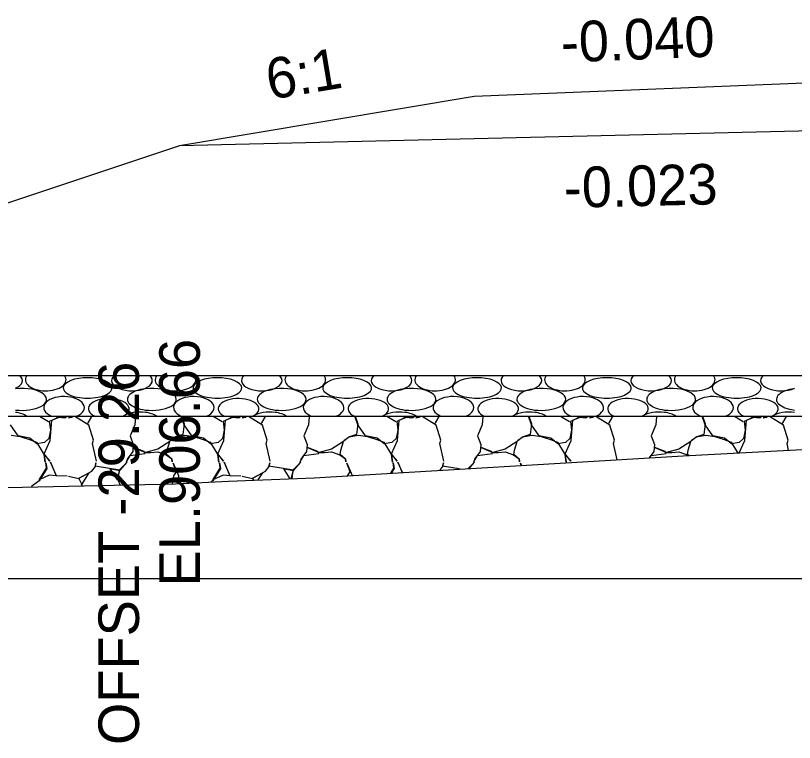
# Model space of a CAD drawing. Extents: x -26 to 4781, y -31 to 24738.
# Drawn here: x 2266.7 to 2285.89, y 14995.97 to 15013.86 of the extents above; entities that cross this region are included whole.
import ezdxf

# ---------------------------------------------------------------- set-up
doc = ezdxf.new("R2010")
doc.units = 0
for name, color, linetype in [('DESIGN - SHEET - Light Grid', 7, 'Continuous'), ('DESIGN - TRANSPORTATION - Proposed Layout Patterning', 7, 'Continuous'), ('DESIGN - TYPICAL - Finished Grade and Subgrade', 7, 'Continuous'), ('DESIGN - TYPICAL - Finished Grade Slopes Text', 7, 'Continuous'), ('DESIGN - TYPICAL - Subgrade Cross Slope Text', 7, 'Continuous'), ('DESIGN - TYPICAL - Subgrade Tie Text', 7, 'Continuous'), ('GEOTECHNICAL – SCRATCH – Level 1', 7, 'Continuous'), ('SURVEY - GROUND - Top of Ground', 7, 'Continuous')]:
    doc.layers.add(name, color=color, linetype=linetype)

msp = doc.modelspace()

# ---------------------------------------------------------------- linework, layer by layer
at = {"layer": 'DESIGN - SHEET - Light Grid'}
msp.add_line((2000, 15000), (2300, 15000), dxfattribs=at)
at = {"layer": 'DESIGN - TRANSPORTATION - Proposed Layout Patterning'}
for p, q in [((2267.288, 15004), (2267.507, 15003.869)), ((2271.568, 15004), (2271.787, 15003.869)), ((2275.848, 15004), (2276.067, 15003.869)), ((2280.128, 15004), (2280.347, 15003.869)), ((2284.408, 15004), (2284.627, 15003.869))]:
    msp.add_line(p, q, dxfattribs=at)
for points in [[(2266.587, 15003.529), (2266.807, 15003.499), (2267.037, 15003.429), (2267.207, 15003.359), (2267.397, 15003.049), (2267.427, 15002.869), (2267.397, 15003.059), (2267.537, 15002.889), (2267.397, 15003.069), (2267.547, 15003.399), (2267.587, 15003.899), (2267.767, 15003.979), (2267.897, 15003.959), (2267.977, 15003.999), (2267.927, 15003.959), (2267.777, 15003.989), (2267.607, 15003.899), (2267.527, 15003.869), (2267.557, 15003.659), (2267.517, 15003.449), (2267.407, 15003.349), (2267.217, 15003.319), (2267.047, 15003.459), (2266.757, 15003.519), (2266.567, 15003.789)], [(2268.687, 15002.889), (2268.587, 15003.329), (2268.617, 15003.409), (2268.497, 15003.779), (2268.157, 15003.989), (2267.997, 15003.959), (2268.087, 15003.979), (2268.083, 15004)], [(2268.571, 15004), (2268.477, 15003.829), (2268.576, 15004)], [(2269.64, 15004), (2269.647, 15003.989), (2269.637, 15003.789), (2269.517, 15003.519), (2269.597, 15003.299), (2269.587, 15003.129), (2269.447, 15002.939), (2269.427, 15002.879), (2269.517, 15003.029), (2269.887, 15003.079), (2269.867, 15003.129), (2269.607, 15003.229), (2269.897, 15003.109), (2270.027, 15003.109), (2270.197, 15003.119), (2270.407, 15003.049), (2270.547, 15002.949), (2270.557, 15002.879), (2270.547, 15002.939), (2270.417, 15003.059), (2270.427, 15003.159), (2270.497, 15003.379), (2270.197, 15003.189), (2269.897, 15003.109)], [(2270.781, 15004), (2270.847, 15003.809), (2270.817, 15003.549), (2270.647, 15003.489), (2270.507, 15003.389), (2270.627, 15003.489), (2270.867, 15003.529), (2271.087, 15003.499), (2271.317, 15003.429), (2271.487, 15003.359), (2271.677, 15003.049), (2271.707, 15002.869), (2271.677, 15003.059), (2271.817, 15002.889), (2271.677, 15003.069), (2271.827, 15003.399), (2271.867, 15003.899), (2272.047, 15003.979), (2272.177, 15003.959), (2272.257, 15003.999), (2272.207, 15003.959), (2272.057, 15003.989), (2271.887, 15003.899), (2271.807, 15003.869), (2271.837, 15003.659), (2271.797, 15003.449), (2271.687, 15003.349), (2271.497, 15003.319), (2271.327, 15003.459), (2271.037, 15003.519), (2270.847, 15003.789), (2270.779, 15004)], [(2272.967, 15002.889), (2272.867, 15003.329), (2272.897, 15003.409), (2272.777, 15003.779), (2272.437, 15003.989), (2272.277, 15003.959), (2272.367, 15003.979), (2272.363, 15004)], [(2272.851, 15004), (2272.757, 15003.829), (2272.856, 15004)], [(2273.92, 15004), (2273.927, 15003.989), (2273.917, 15003.789), (2273.797, 15003.519), (2273.877, 15003.299), (2273.867, 15003.129), (2273.727, 15002.939), (2273.707, 15002.879), (2273.797, 15003.029), (2274.167, 15003.079), (2274.147, 15003.129), (2273.887, 15003.229), (2274.177, 15003.109), (2274.307, 15003.109), (2274.477, 15003.119), (2274.687, 15003.049), (2274.827, 15002.949), (2274.837, 15002.879), (2274.827, 15002.939), (2274.697, 15003.059), (2274.707, 15003.159), (2274.777, 15003.379), (2274.477, 15003.189), (2274.177, 15003.109)], [(2275.061, 15004), (2275.127, 15003.809), (2275.097, 15003.549), (2274.927, 15003.489), (2274.787, 15003.389), (2274.907, 15003.489), (2275.147, 15003.529), (2275.367, 15003.499), (2275.597, 15003.429), (2275.767, 15003.359), (2275.957, 15003.049), (2275.987, 15002.869), (2275.957, 15003.059), (2276.097, 15002.889), (2275.957, 15003.069), (2276.107, 15003.399), (2276.147, 15003.899), (2276.327, 15003.979), (2276.457, 15003.959), (2276.537, 15003.999), (2276.487, 15003.959), (2276.337, 15003.989), (2276.167, 15003.899), (2276.087, 15003.869), (2276.117, 15003.659), (2276.077, 15003.449), (2275.967, 15003.349), (2275.777, 15003.319), (2275.607, 15003.459), (2275.317, 15003.519), (2275.127, 15003.789), (2275.059, 15004)], [(2277.247, 15002.889), (2277.147, 15003.329), (2277.177, 15003.409), (2277.057, 15003.779), (2276.717, 15003.989), (2276.557, 15003.959), (2276.647, 15003.979), (2276.643, 15004)], [(2277.131, 15004), (2277.037, 15003.829), (2277.136, 15004)], [(2278.2, 15004), (2278.207, 15003.989), (2278.197, 15003.789), (2278.077, 15003.519), (2278.157, 15003.299), (2278.147, 15003.129), (2278.007, 15002.939), (2277.987, 15002.879), (2278.077, 15003.029), (2278.447, 15003.079), (2278.427, 15003.129), (2278.167, 15003.229), (2278.457, 15003.109), (2278.587, 15003.109), (2278.757, 15003.119), (2278.967, 15003.049), (2279.107, 15002.949), (2279.117, 15002.879), (2279.107, 15002.939), (2278.977, 15003.059), (2278.987, 15003.159), (2279.057, 15003.379), (2278.757, 15003.189), (2278.457, 15003.109)], [(2279.341, 15004), (2279.407, 15003.809), (2279.377, 15003.549), (2279.207, 15003.489), (2279.067, 15003.389), (2279.187, 15003.489), (2279.427, 15003.529), (2279.647, 15003.499), (2279.877, 15003.429), (2280.047, 15003.359), (2280.237, 15003.049), (2280.267, 15002.869), (2280.237, 15003.059), (2280.377, 15002.889), (2280.237, 15003.069), (2280.387, 15003.399), (2280.427, 15003.899), (2280.607, 15003.979), (2280.737, 15003.959), (2280.817, 15003.999), (2280.767, 15003.959), (2280.617, 15003.989), (2280.447, 15003.899), (2280.367, 15003.869), (2280.397, 15003.659), (2280.357, 15003.449), (2280.247, 15003.349), (2280.057, 15003.319), (2279.887, 15003.459), (2279.597, 15003.519), (2279.407, 15003.789), (2279.339, 15004)], [(2281.518, 15002.927), (2281.427, 15003.329), (2281.457, 15003.409), (2281.337, 15003.779), (2280.997, 15003.989), (2280.837, 15003.959), (2280.927, 15003.979), (2280.923, 15004)], [(2281.411, 15004), (2281.317, 15003.829), (2281.416, 15004)], [(2282.48, 15004), (2282.487, 15003.989), (2282.477, 15003.789), (2282.357, 15003.519), (2282.437, 15003.299), (2282.427, 15003.129), (2282.313, 15002.974)], [(2283.621, 15004), (2283.687, 15003.809), (2283.657, 15003.549), (2283.487, 15003.489), (2283.347, 15003.389), (2283.467, 15003.489), (2283.707, 15003.529), (2283.927, 15003.499), (2284.157, 15003.429), (2284.327, 15003.359), (2284.49, 15003.093)], [(2284.529, 15003.095), (2284.667, 15003.399), (2284.707, 15003.899), (2284.887, 15003.979), (2285.017, 15003.959), (2285.097, 15003.999), (2285.047, 15003.959), (2284.897, 15003.989), (2284.727, 15003.899), (2284.647, 15003.869), (2284.677, 15003.659), (2284.637, 15003.449), (2284.527, 15003.349), (2284.337, 15003.319), (2284.167, 15003.459), (2283.877, 15003.519), (2283.687, 15003.789), (2283.619, 15004)], [(2285.746, 15003.158), (2285.707, 15003.329), (2285.737, 15003.409), (2285.617, 15003.779), (2285.277, 15003.989), (2285.117, 15003.959), (2285.207, 15003.979), (2285.203, 15004)], [(2285.691, 15004), (2285.597, 15003.829), (2285.696, 15004)], [(2283.287, 15003.031), (2283.257, 15003.059), (2283.267, 15003.159), (2283.337, 15003.379), (2283.037, 15003.189), (2282.737, 15003.109)], [(2282.325, 15002.975), (2282.357, 15003.029), (2282.727, 15003.079), (2282.707, 15003.129), (2282.447, 15003.229), (2282.737, 15003.109), (2282.867, 15003.109), (2283.037, 15003.119), (2283.247, 15003.049), (2283.273, 15003.03)], [(2267.967, 15002.519), (2267.707, 15002.529), (2267.557, 15002.869), (2267.697, 15002.529), (2267.527, 15002.549), (2267.277, 15002.429), (2267.457, 15002.719), (2267.437, 15002.849), (2267.467, 15002.709), (2267.277, 15002.409), (2267.087, 15002.269), (2267.086, 15002.256)], [(2267.997, 15002.519), (2268.257, 15002.469), (2268.327, 15002.319), (2268.507, 15002.609), (2268.247, 15002.469), (2268.577, 15002.649), (2268.667, 15002.759), (2268.677, 15002.849), (2268.657, 15002.779), (2269.007, 15002.719), (2269.197, 15002.429), (2269.267, 15002.669), (2269.007, 15002.709), (2269.267, 15002.659), (2269.447, 15002.869), (2269.247, 15002.669), (2269.217, 15002.429), (2269.27, 15002.303)], [(2270.562, 15002.33), (2270.597, 15002.529), (2270.657, 15002.629), (2270.577, 15002.839), (2270.707, 15002.539), (2270.714, 15002.336)], [(2272.247, 15002.519), (2271.987, 15002.529), (2271.837, 15002.869), (2271.977, 15002.529), (2271.807, 15002.549), (2271.557, 15002.429), (2271.737, 15002.719), (2271.717, 15002.849), (2271.747, 15002.709), (2271.557, 15002.409), (2271.518, 15002.38)], [(2272.676, 15002.43), (2272.787, 15002.609), (2272.527, 15002.469), (2272.857, 15002.649), (2272.947, 15002.759), (2272.957, 15002.849), (2272.937, 15002.779), (2273.287, 15002.719), (2273.457, 15002.459)], [(2273.486, 15002.46), (2273.547, 15002.669), (2273.287, 15002.709), (2273.547, 15002.659), (2273.727, 15002.869), (2273.527, 15002.669), (2273.501, 15002.461)], [(2274.878, 15002.53), (2274.937, 15002.629), (2274.857, 15002.839), (2274.987, 15002.539), (2274.987, 15002.537)], [(2275.939, 15002.594), (2276.017, 15002.719), (2275.997, 15002.849), (2276.027, 15002.709), (2275.955, 15002.595)], [(2276.231, 15002.611), (2276.117, 15002.869), (2276.223, 15002.611)], [(2277.151, 15002.666), (2277.227, 15002.759), (2277.237, 15002.849), (2277.217, 15002.779), (2277.567, 15002.719), (2277.584, 15002.692)], [(2277.87, 15002.709), (2278.007, 15002.869), (2277.846, 15002.708)], [(2279.157, 15002.786), (2279.137, 15002.839), (2279.16, 15002.786)], [(2280.401, 15002.86), (2280.397, 15002.869), (2280.401, 15002.86)], [(2277.65, 15002.696), (2277.567, 15002.709), (2277.638, 15002.695)], [(2272.277, 15002.519), (2272.537, 15002.469), (2272.557, 15002.426)], [(2268.34, 15002.283), (2268.317, 15002.329), (2268.338, 15002.283)]]:
    msp.add_lwpolyline(points, dxfattribs=at)
for centre, major_axis, ratio, start_param, end_param in [((2266.365, 15004.875), (-0.501, 0), 0.5, 2.292187, 3.663383), ((2267.438, 15004.895), (-0.501, 0), 0.54, 5.885335, 7.825415), ((2267.438, 15004.895), (-0.501, 0), 0.54, 1.545388, 3.539443), ((2268.47, 15004.695), (-0.602, 0), 0.416667, 2.446, 6.978671), ((2269.563, 15004.875), (-0.501, 0), 0.5, 5.761395, 8.575372), ((2269.564, 15004.875), (-0.501, 0), 0.5, 2.292187, 3.663383), ((2270.636, 15004.895), (-0.501, 0), 0.54, 5.885335, 7.825415), ((2270.636, 15004.895), (-0.501, 0), 0.54, 1.545388, 3.539443), ((2271.669, 15004.695), (-0.602, 0), 0.416667, 2.446, 6.978671), ((2272.762, 15004.875), (-0.501, 0), 0.5, 5.761395, 8.575372), ((2272.762, 15004.875), (-0.501, 0), 0.5, 2.292187, 3.663383), ((2273.835, 15004.895), (-0.501, 0), 0.54, 5.885335, 7.825415), ((2273.835, 15004.895), (-0.501, 0), 0.54, 1.545388, 3.539443), ((2274.868, 15004.695), (-0.602, 0), 0.416667, 2.446, 6.978671), ((2275.961, 15004.875), (-0.501, 0), 0.5, 5.761395, 8.575372), ((2275.961, 15004.875), (-0.501, 0), 0.5, 2.292187, 3.663383), ((2277.034, 15004.895), (-0.501, 0), 0.54, 5.885335, 7.825415), ((2277.034, 15004.895), (-0.501, 0), 0.54, 1.545388, 3.539443), ((2278.067, 15004.695), (-0.602, 0), 0.416667, 2.446, 6.978671), ((2279.16, 15004.875), (-0.501, 0), 0.5, 5.761395, 8.575372), ((2279.16, 15004.875), (-0.501, 0), 0.5, 2.292187, 3.663383), ((2280.233, 15004.895), (-0.501, 0), 0.54, 5.885335, 7.825415), ((2280.233, 15004.895), (-0.501, 0), 0.54, 1.545388, 3.539443), ((2281.266, 15004.695), (-0.602, 0), 0.416667, 2.446, 6.978671), ((2282.359, 15004.875), (-0.501, 0), 0.5, 5.761395, 8.575372), ((2282.359, 15004.875), (-0.501, 0), 0.5, 2.292187, 3.663383), ((2283.432, 15004.895), (-0.501, 0), 0.54, 5.885335, 7.825415), ((2283.432, 15004.895), (-0.501, 0), 0.54, 1.545388, 3.539443), ((2284.465, 15004.695), (-0.602, 0), 0.416667, 2.446, 6.978671), ((2285.557, 15004.875), (-0.501, 0), 0.5, 5.761395, 8.575372), ((2266.856, 15004.414), (-0.602, 0), 0.45, 3.602876, 4.982641), ((2270.054, 15004.414), (-0.602, 0), 0.45, 4.982641, 5.821976), ((2270.055, 15004.414), (-0.602, 0), 0.45, 3.602876, 4.982641), ((2273.253, 15004.414), (-0.602, 0), 0.45, 4.982641, 5.821976), ((2273.254, 15004.414), (-0.602, 0), 0.45, 3.602876, 4.982641), ((2276.452, 15004.414), (-0.602, 0), 0.45, 4.982641, 5.821976), ((2276.453, 15004.414), (-0.602, 0), 0.45, 3.602876, 4.982641), ((2279.651, 15004.414), (-0.602, 0), 0.45, 4.982641, 5.821976), ((2279.651, 15004.414), (-0.602, 0), 0.45, 3.602876, 4.982641), ((2282.85, 15004.414), (-0.602, 0), 0.45, 4.982641, 5.821976), ((2282.85, 15004.414), (-0.602, 0), 0.45, 3.602876, 4.982641), ((2286.049, 15004.414), (-0.602, 0), 0.45, 4.982641, 5.821976), ((2266.856, 15004.413), (-0.602, 0), 0.45, 1.300445, 3.602877), ((2267.889, 15004.213), (-0.501, 0), 0.54, 4.698848, 7.188458), ((2267.889, 15004.213), (-0.501, 0), 0.54, 2.23632, 4.691622), ((2268.47, 15004.694), (-0.602, 0), 0.416667, 0.695486, 2.446), ((2270.054, 15004.413), (-0.602, 0), 0.45, 5.821976, 7.58363), ((2270.055, 15004.413), (-0.602, 0), 0.45, 1.300445, 3.602877), ((2271.088, 15004.213), (-0.501, 0), 0.54, 4.698848, 7.188458), ((2271.088, 15004.213), (-0.501, 0), 0.54, 2.23632, 4.691622), ((2271.669, 15004.694), (-0.602, 0), 0.416667, 0.695486, 2.446), ((2273.253, 15004.413), (-0.602, 0), 0.45, 5.821976, 7.58363), ((2273.254, 15004.413), (-0.602, 0), 0.45, 1.300445, 3.602877), ((2274.286, 15004.213), (-0.501, 0), 0.54, 4.698848, 7.188458), ((2274.286, 15004.213), (-0.501, 0), 0.54, 2.23632, 4.691622), ((2274.868, 15004.694), (-0.602, 0), 0.416667, 0.695486, 2.446), ((2276.452, 15004.413), (-0.602, 0), 0.45, 5.821976, 7.58363), ((2276.453, 15004.413), (-0.602, 0), 0.45, 1.300445, 3.602877), ((2277.485, 15004.213), (-0.501, 0), 0.54, 4.698848, 7.188458), ((2277.485, 15004.213), (-0.501, 0), 0.54, 2.23632, 4.691622), ((2278.067, 15004.694), (-0.602, 0), 0.416667, 0.695486, 2.446), ((2279.651, 15004.413), (-0.602, 0), 0.45, 5.821976, 7.58363), ((2279.651, 15004.413), (-0.602, 0), 0.45, 1.300445, 3.602877), ((2280.684, 15004.213), (-0.501, 0), 0.54, 4.698848, 7.188458), ((2280.684, 15004.213), (-0.501, 0), 0.54, 2.23632, 4.691622), ((2281.266, 15004.694), (-0.602, 0), 0.416667, 0.695486, 2.446), ((2282.85, 15004.413), (-0.602, 0), 0.45, 5.821976, 7.58363), ((2282.85, 15004.413), (-0.602, 0), 0.45, 1.300445, 3.602877), ((2283.883, 15004.213), (-0.501, 0), 0.54, 4.698848, 7.188458), ((2283.883, 15004.213), (-0.501, 0), 0.54, 2.23632, 4.691622), ((2284.465, 15004.694), (-0.602, 0), 0.416667, 0.695486, 2.446), ((2286.049, 15004.413), (-0.602, 0), 0.45, 5.821976, 7.58363), ((2268.992, 15004.183), (-0.501, 0), 0.5, 4.691313, 7.100807), ((2268.992, 15004.183), (-0.501, 0), 0.5, 2.323971, 4.683059), ((2272.19, 15004.183), (-0.501, 0), 0.5, 4.691313, 7.100807), ((2272.19, 15004.183), (-0.501, 0), 0.5, 2.323971, 4.683059), ((2275.389, 15004.183), (-0.501, 0), 0.5, 4.691313, 7.100807), ((2275.389, 15004.183), (-0.501, 0), 0.5, 2.323971, 4.683059), ((2278.588, 15004.183), (-0.501, 0), 0.5, 4.691313, 7.100807), ((2278.588, 15004.183), (-0.501, 0), 0.5, 2.323971, 4.683059), ((2281.787, 15004.183), (-0.501, 0), 0.5, 4.691313, 7.100807), ((2281.787, 15004.183), (-0.501, 0), 0.5, 2.323971, 4.683059), ((2284.986, 15004.183), (-0.501, 0), 0.5, 4.691313, 7.100807), ((2284.986, 15004.183), (-0.501, 0), 0.5, 2.323971, 4.683059), ((2266.565, 15003.852), (-0.501, 0), 0.5, 3.773245, 4.449052), ((2269.764, 15003.852), (-0.501, 0), 0.5, 4.449052, 5.651533), ((2269.764, 15003.852), (-0.501, 0), 0.5, 3.773245, 4.449052), ((2272.962, 15003.852), (-0.501, 0), 0.5, 4.449052, 5.651533), ((2272.963, 15003.852), (-0.501, 0), 0.5, 3.773245, 4.449052), ((2276.161, 15003.852), (-0.501, 0), 0.5, 4.449052, 5.651533), ((2276.162, 15003.852), (-0.501, 0), 0.5, 3.773245, 4.449052), ((2279.36, 15003.852), (-0.501, 0), 0.5, 4.449052, 5.651533), ((2279.361, 15003.852), (-0.501, 0), 0.5, 3.773245, 4.449052), ((2282.559, 15003.852), (-0.501, 0), 0.5, 4.449052, 5.651533), ((2282.56, 15003.852), (-0.501, 0), 0.5, 3.773245, 4.449052), ((2285.758, 15003.852), (-0.501, 0), 0.5, 4.449052, 5.651533)]:
    msp.add_ellipse(centre, major_axis=major_axis, ratio=ratio, start_param=start_param, end_param=end_param, dxfattribs=at)
at = {"layer": 'DESIGN - TYPICAL - Finished Grade and Subgrade'}
for p, q in [((2288, 15012.271), (2278, 15011.871)), ((2278, 15011.871), (2270.737, 15010.66)), ((2288, 15011.061), (2278, 15010.829)), ((2278, 15010.829), (2270.737, 15010.66)), ((2270.737, 15010.66), (2243.957, 15001.733))]:
    msp.add_line(p, q, dxfattribs=at)
at = {"layer": 'GEOTECHNICAL – SCRATCH – Level 1'}
for p, q in [((2253.757, 15005), (2305.655, 15005)), ((2250.757, 15004), (2301.225, 15004))]:
    msp.add_line(p, q, dxfattribs=at)
at = {"layer": 'SURVEY - GROUND - Top of Ground'}
msp.add_lwpolyline([(2242.777, 15001.702), (2245.687, 15001.78), (2250.183, 15001.901), (2255.593, 15002.038), (2257.815, 15002.059), (2270.635, 15002.332), (2271.939, 15002.403), (2274.057, 15002.481), (2283.146, 15003.024), (2286.395, 15003.192), (2294.105, 15003.456), (2296.424, 15003.479), (2297.254, 15003.554), (2300.072, 15003.713), (2303.43, 15004.549), (2308.947, 15005.668), (2311.406, 15006.319), (2311.769, 15006.357), (2313.689, 15006.493)], dxfattribs=at)

# ---------------------------------------------------------------- texts
at = {"layer": 'DESIGN - TYPICAL - Finished Grade Slopes Text'}
for s, rotation, p in [('-0.040', 2.2906, (2280.149, 15012.707)), ('6:1', 9.4623, (2272.957, 15011.79))]:
    msp.add_text(s, height=1, rotation=rotation, dxfattribs=at).set_placement(p)
at = {"layer": 'DESIGN - TYPICAL - Subgrade Cross Slope Text'}
msp.add_text('-0.023', height=1, rotation=1.3288, dxfattribs=at).set_placement((2280.214, 15009.13))
at = {"layer": 'DESIGN - TYPICAL - Subgrade Tie Text'}
for s, p in [('EL.906.66', (2271.237, 14999.807)), ('OFFSET -29.26', (2269.737, 14995.904))]:
    msp.add_text(s, height=1, rotation=90, dxfattribs=at).set_placement(p)

doc.saveas('drawing.dxf')
